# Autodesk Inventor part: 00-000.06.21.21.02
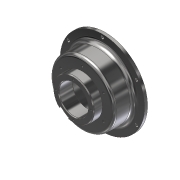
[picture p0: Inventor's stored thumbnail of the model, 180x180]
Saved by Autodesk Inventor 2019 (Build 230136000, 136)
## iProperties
Created: 2019-01
Part Number: 00-000.06.21.21.02
Material: Steel, Mild
Document SubType Name: Modeling
Designer: m.vorobev
Density: 7.85 g/cm^3
Appearance: Semi-Polished
Author: m.vorobev
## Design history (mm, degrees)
sketch "Sketch1"
  geometry: L1 (145, 0)-(100, 0); L2 (100, 0)-(100, 15); L3 (100, 15)-(145, 15); L4 (145, 15)-(145, 0); L5 (100, 15)-(110, 15); L6 (110, 15)-(110, 38.134); L7 (110, 38.134)-(100, 38.134); L8 (100, 38.134)-(100, 15); L9 (110, 38.134)-(100, 38.134); L10 (100, 38.134)-(100, 85); L11 (100, 85)-(110, 85); L12 (110, 85)-(110, 38.134); L13 (100, 85)-(70, 85); L14 (70, 85)-(70, 67); L15 (70, 67)-(100, 67); L16 (100, 67)-(100, 85); L17 (50, 65)-(70, 65); L18 (70, 65)-(70, 115); L19 (70, 115)-(50, 115); L20 (50, 115)-(50, 65); L21 (0, 36.823)-(0, 0); L22 (100, 0)-(125, 0); L23 (100, 4)-(100, 0); L24 (145, 0)-(125, 0); L25 (125, 0)-(125, 5); L26 (125, 5)-(145, 5); L27 (145, 5)-(145, 0); 1 further point
  constraints: 54 end point, 12 parallel, 7 horizontal, 6 perpendicular, 2 collinear, 1 horizontal alignment, 1 midpoint
  dimensions: "d0" = 290 diameter of L4 L21; "d1" = 220 diameter of L12 L21; "d2" = 140 diameter of L18 L21; "d3" = 200 diameter of L10 L21; "d4" = 15 distance of L3.end L1.start; "d7" = 50 distance of L19.end L17.start; "d8" = 100 diameter of L20 L21; "d9" = 115 distance between parallel lines of L1 L19; "d87" = 30 distance between parallel lines of L19 L11; "d88" = 52 distance between parallel lines of L15 L3; "d89" = 5 distance of L24.end L25.end; "d90" = 250 diameter of L25 L21
revolve "Revolution1" sketch "Sketch1" stored, may be unused: angle "d16" = 90 deg
fillet "Fillet1" dims "d17" = 10, "d18" = 15, "d19" = 3
chamfer "Chamfer1" distance "d20" = 3; stored, may be unused: second distance "d21" = 2, angle "d22" = 45 deg
chamfer "Chamfer2" distance "d23" = 2.5; stored, may be unused: second distance "d24" = 2, angle "d25" = 45 deg
sketch "Sketch2"
  geometry: L1 (43.589, 90)-(-43.589, 90); L2 (-43.589, 90)-(-43.589, 101.006); L3 (-43.589, 101.006)-(43.589, 101.006); L4 (43.589, 101.006)-(43.589, 90); A1 r 100 centre (0, 0) between (43.589, 90) and (-43.589, 90) reference; 1 further point
  constraints: 8 end point, 2 parallel, 2 point on circle, 1 centre point, 1 horizontal, 1 perpendicular, 1 other
  dimensions: "d27" = 90 distance from line of point (0, 0) L1
extrude "Extrusion1" join sketch "Sketch2" distance "d28" = 22; taper "d29" = 0 deg
sketch "Sketch3"
  geometry: 6 further points; 1 other entity
  constraints: 2 other
hole "Hole1" sketch "Sketch3" diameter "d30" = 20; stored, may be unused: countersink angle "d34" = 90 deg, drill point angle "d36" = 118 deg; dims "d31" = 6, "d32" = 4, "d33" = 2, "d35" = 25
chamfer "Chamfer3" distance "d37" = 1; stored, may be unused: second distance "d38" = 2, angle "d39" = 45 deg
pattern_circular "Circular Pattern1" dims angle "d41" = 360 deg
sketch "Sketch6"
  geometry: L1 (0, 0)-(0, -60)
  constraints: 2 end point, 1 vertical
  dimensions: "d58" = 60 distance of L1.start L1.end
hole "Hole3" sketch "Sketch6" at (0, -60) diameter "d59" = 6.647; stored, may be unused: countersink angle "d63" = 90 deg, drill point angle "d65" = 118 deg; dims "d60" = 59.25, "d61" = 16, "d62" = 2, "d64" = 100.7
pattern_circular "Circular Pattern3" dims angle "d67" = 360 deg
sketch "Sketch7"
  geometry: L1 (0, 0)-(0, 135)
  constraints: 2 end point, 1 vertical
  dimensions: "d69" = 135 distance of L1.start L1.end
hole "Hole4" sketch "Sketch7" at (0, 135) diameter "d70" = 11; stored, may be unused: countersink angle "d74" = 90 deg, drill point angle "d76" = 118 deg; dims "d71" = 59.25, "d72" = 16, "d73" = 2, "d75" = 100.7
pattern_circular "Circular Pattern4" dims angle "d78" = 360 deg
sketch "Sketch8"
  geometry: L1 (87.178, 0)-(-5.485, 0); L2 (-5.485, 0)-(-5.485, -67.713); L3 (-5.485, -67.713)-(87.178, -67.713); L4 (87.178, -67.713)-(87.178, 0); C1 r 25 at (43.589, -22); 1 further point
  constraints: 8 end point, 2 parallel, 1 centre point, 1 coincident, 1 horizontal, 1 perpendicular
  dimensions: "d80" = 50 diameter of C1
extrude "Extrusion2" cut sketch "Sketch8" stored distance "d81" = 20; taper "d82" = 0 deg
pattern_circular "Circular Pattern5" dims angle "d84" = 360 deg
delete_face "Delete Face1"
delete_face "Delete Face2"
delete_face "Delete Face3"
delete_face "Delete Face4"
fillet "Fillet3" dims "d86" = 3
sketch "Sketch9"
  geometry: L1 (-73.171, -90.736)-(-41.994, -108.736); L2 (-41.994, -108.736)-(-13.412, -59.229); L3 (-13.412, -59.229)-(-44.588, -41.229); L4 (-44.588, -41.229)-(-73.171, -90.736); L5 (0, 0)-(-50.677, 0); L6 (-50.677, 0)-(-50.677, 24.836); L7 (-50.677, 24.836)-(0, 24.836); L8 (0, 24.836)-(0, 0); L9 (0, 0)-(-29, -50.229); C1 r 70 at (0, 0) reference
  constraints: 18 end point, 4 parallel, 3 perpendicular, 1 horizontal, 1 midpoint
  dimensions: "d91" = 60 deg angle of L5 L9; "d92" = 128 dimension on C1 L3; "d96" = 36 distance of L2.end L3.end
extrude "Extrusion3" cut sketch "Sketch9" distance "d93" = 28; taper "d94" = 0 deg
fillet "Fillet4" dims "d95" = 0.8
sketch "Sketch10"
  geometry: L1 (0, 0)-(0, 85)
  constraints: 2 end point, 1 vertical
  dimensions: "d97" = 85 distance of L1.start L1.end
hole "Hole5" sketch "Sketch10" at (0, 85) diameter "d98" = 8.376; stored, may be unused: countersink angle "d102" = 90 deg, drill point angle "d104" = 118 deg; dims "d99" = 20, "d100" = 4, "d101" = 2, "d103" = 27.3
pattern_circular "Circular Pattern6" dims angle "d106" = 360 deg
delete_face "Delete Face5"
body "Solid1"
